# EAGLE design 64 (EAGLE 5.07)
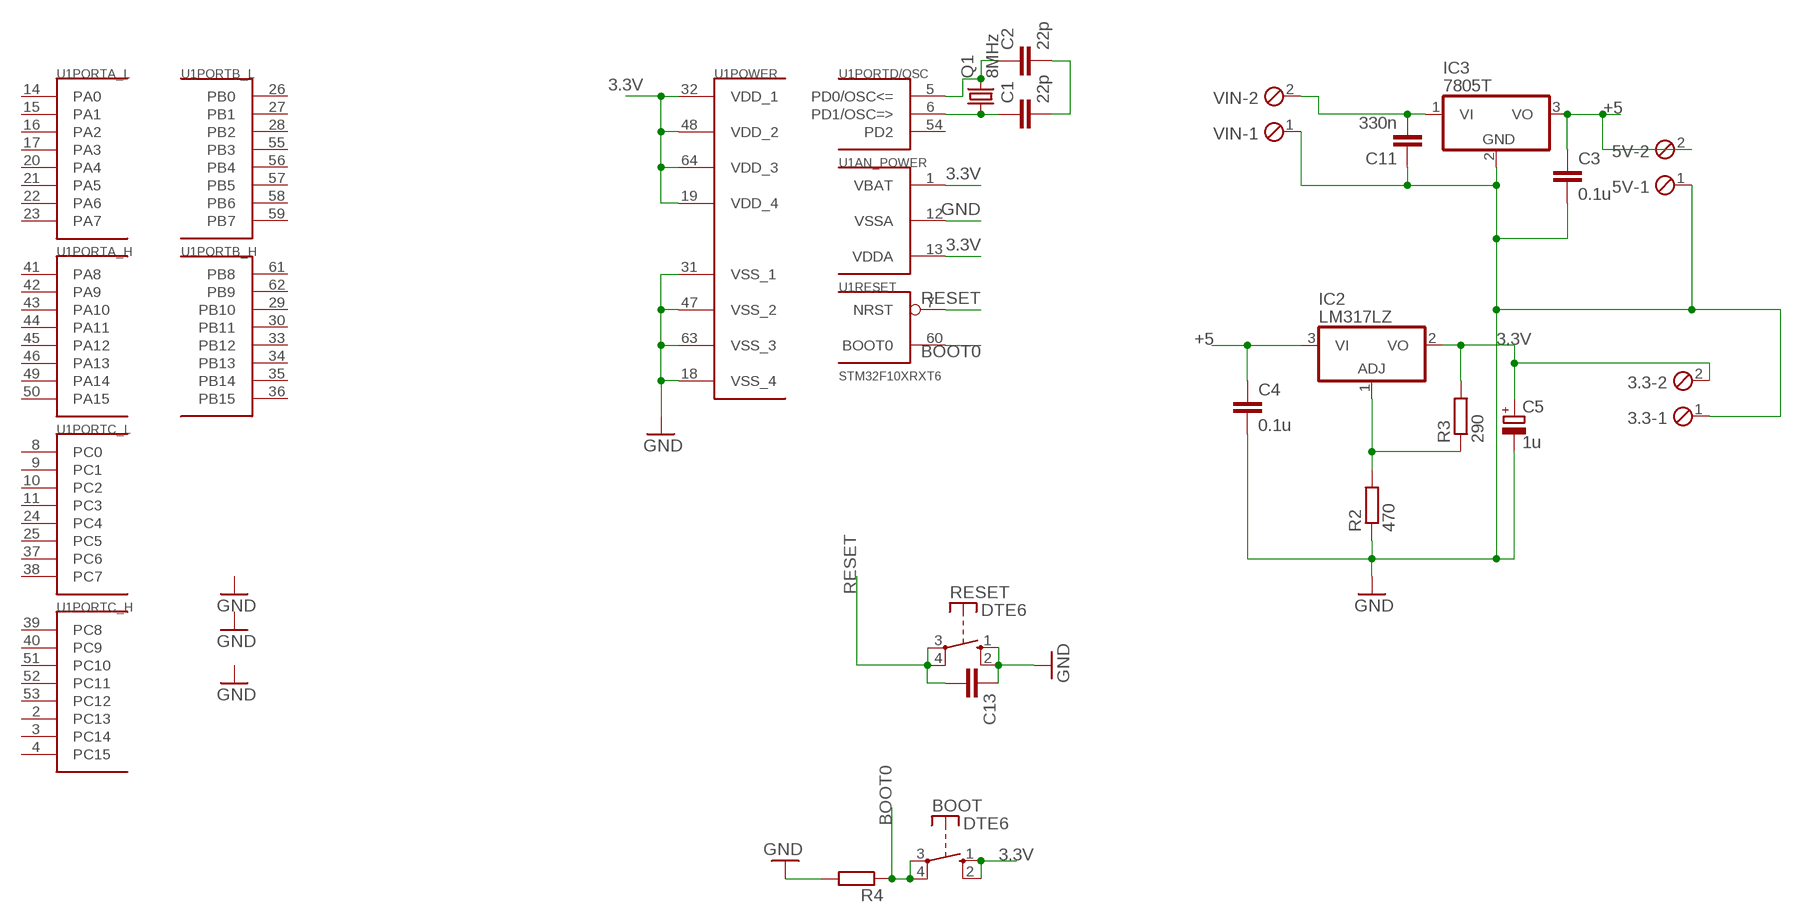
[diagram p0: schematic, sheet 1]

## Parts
3.3  MPT2  [2POL254]
5V  MPT2  [2POL254]
BOOT  DTE6  [DTE6]
C1  22p  C-EUC0805  [C0805]
C2  22p  C-EUC0805  [C0805]
C3  0.1u  C-EUC0805  [C0805]
C4  0.1u  C-EUC0805  [C0805]
C5  1u  CPOL-EUE2.5-6  [E2,5-6]
C11  330n  C-EUC0805  [C0805]
C13  C-EUC0805K  [C0805K]
IC2  LM317LZ  [TO92]
IC3  7805T  [TO220H]
Q1  8MHz  CRYSTALHC49S  [HC49/S]
R2  470  R-EU_R0805  [R0805]
R3  290  R-EU_R0805  [R0805]
R4  R-EU_R0805  [R0805]
RESET  DTE6  [DTE6]
U1  STM32F10XRXT6  [TQFP64]
VIN  MPT2  [2POL254]

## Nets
3.3V: 3.3.2 BOOT.1(S) BOOT.2(S) C5.+ IC2.2(VO) R3.2 U1.1(AN_POWER:VBAT) U1.13(AN_POWER:VDDA) U1.19(POWER:VDD_4) U1.32(POWER:VDD_1) U1.48(POWER:VDD_2) U1.64(POWER:VDD_3)
+5: 5V.2 C3.1 C4.1 IC2.3(VI) IC3.3(VO)
BOOT0: BOOT.3(P) BOOT.4(P) R4.1 U1.60(RESET:BOOT0)
GND: 3.3.1 5V.1 C3.2 C4.2 C5.- C11.1 C13.1 IC3.2(GND) R2.1 R4.2 RESET.1(S) RESET.2(S) U1.12(AN_POWER:VSSA) U1.18(POWER:VSS_4) U1.31(POWER:VSS_1) U1.47(POWER:VSS_2) U1.63(POWER:VSS_3) VIN.1
N$1: C1.2 C2.2
N$5: IC2.1(ADJ) R2.2 R3.1
N$8: C1.1 Q1.1 U1.6(PORTD/OSC:PD1/OSC=>)
N$9: C2.1 Q1.2 U1.5(PORTD/OSC:PD0/OSC<=)
N$36: C11.2 IC3.1(VI) VIN.2
RESET: C13.2 RESET.3(P) RESET.4(P) U1.7(RESET:NRST)
Unconnected: U1.2(PORTC_H:PC13) U1.3(PORTC_H:PC14) U1.4(PORTC_H:PC15) U1.8(PORTC_L:PC0) U1.9(PORTC_L:PC1) U1.10(PORTC_L:PC2) U1.11(PORTC_L:PC3) U1.14(PORTA_L:PA0) U1.15(PORTA_L:PA1) U1.16(PORTA_L:PA2) U1.17(PORTA_L:PA3) U1.20(PORTA_L:PA4) U1.21(PORTA_L:PA5) U1.22(PORTA_L:PA6) U1.23(PORTA_L:PA7) U1.24(PORTC_L:PC4) U1.25(PORTC_L:PC5) U1.26(PORTB_L:PB0) U1.27(PORTB_L:PB1) U1.28(PORTB_L:PB2) U1.29(PORTB_H:PB10) U1.30(PORTB_H:PB11) U1.33(PORTB_H:PB12) U1.34(PORTB_H:PB13) U1.35(PORTB_H:PB14) U1.36(PORTB_H:PB15) U1.37(PORTC_L:PC6) U1.38(PORTC_L:PC7) U1.39(PORTC_H:PC8) U1.40(PORTC_H:PC9) U1.41(PORTA_H:PA8) U1.42(PORTA_H:PA9) U1.43(PORTA_H:PA10) U1.44(PORTA_H:PA11) U1.45(PORTA_H:PA12) U1.46(PORTA_H:PA13) U1.49(PORTA_H:PA14) U1.50(PORTA_H:PA15) U1.51(PORTC_H:PC10) U1.52(PORTC_H:PC11) U1.53(PORTC_H:PC12) U1.54(PORTD/OSC:PD2) U1.55(PORTB_L:PB3) U1.56(PORTB_L:PB4) U1.57(PORTB_L:PB5) U1.58(PORTB_L:PB6) U1.59(PORTB_L:PB7) U1.61(PORTB_H:PB8) U1.62(PORTB_H:PB9)

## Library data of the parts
3.3 5V VIN = con-phoenix-254:MPT2: PHOENIX CONNECTOR
BOOT RESET = switch-misc:DT: ITT SWITCH
C1-C4 C11 C13 = resistor:C-EU: CAPACITOR, European symbol
C5 = resistor:CPOL-EU: POLARIZED CAPACITOR, European symbol
IC2 = linear:*317: Positive VOLTAGE REGULATOR
IC3 = linear:78*: Positive VOLTAGE REGULATOR Source: http://cache.national.com/ds/LM/LM78L05.pdf http://www.fairchildsemi.com/ds/LM/LM7805.pdf
Q1 = crystal:CRYSTAL: CRYSTAL
R2-R4 = resistor:R-EU_: RESISTOR, European symbol
U1 = stm32:STM32F10XRXT6: STM32F101/103 64pin LQFP

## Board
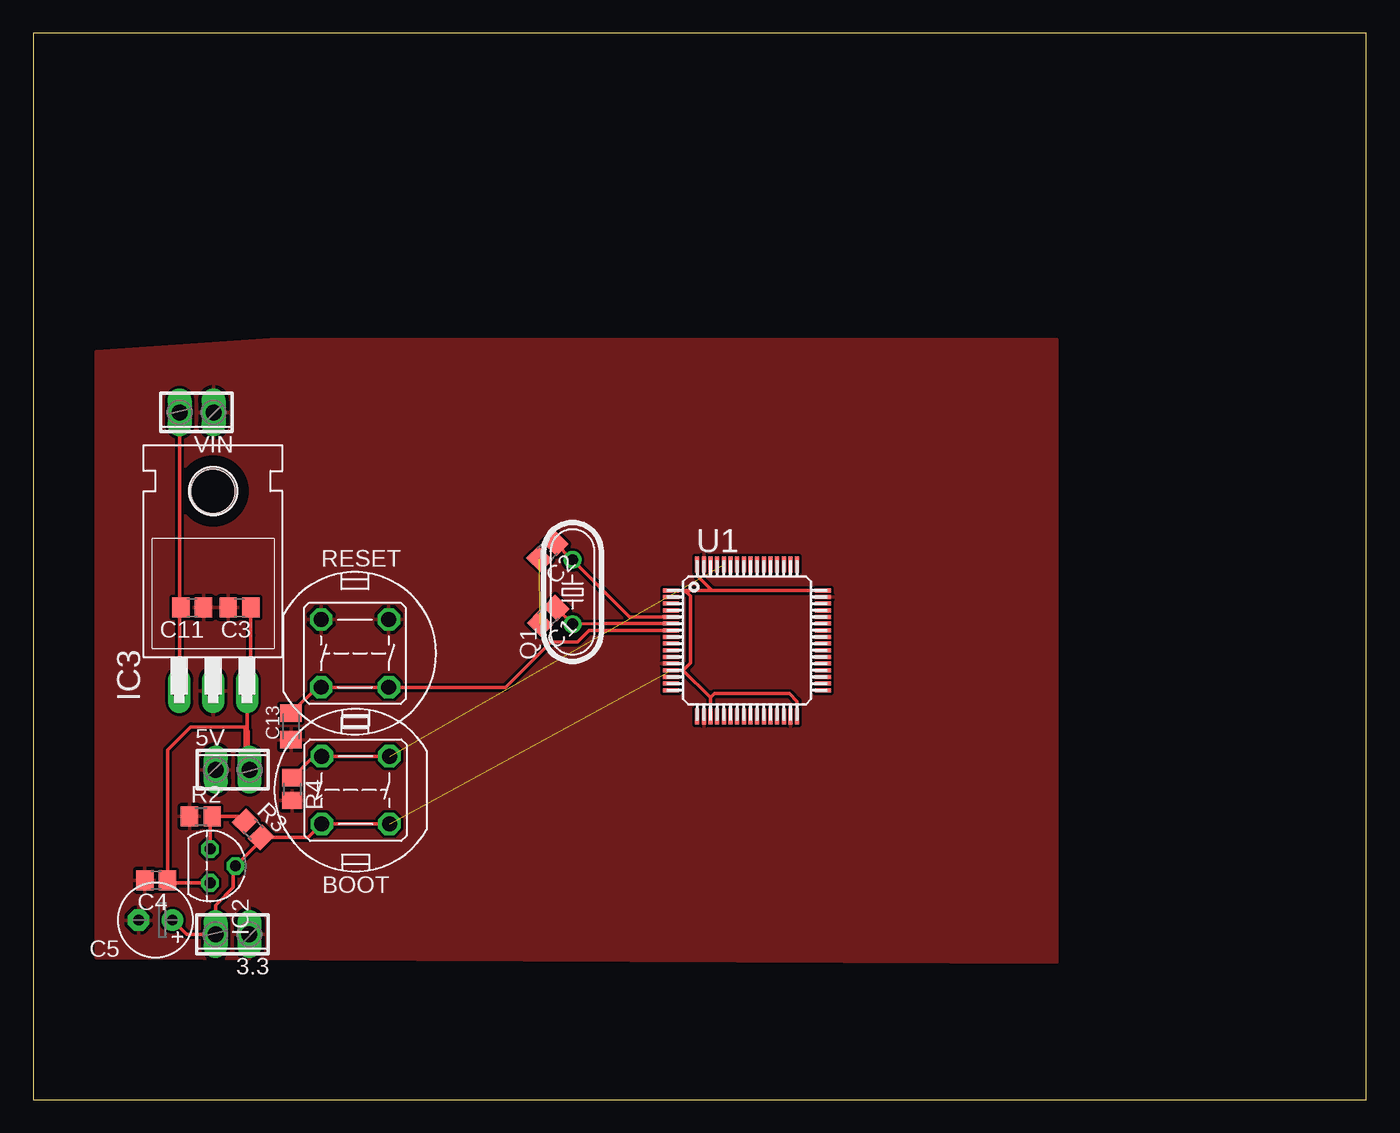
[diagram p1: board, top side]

Size 100 x 80 mm. Coordinates in mm from the lower left corner, seen from the top.
Outline: 0,0 100,0 100,80 0,80 0,0
Copper layers (1*16): Top 0.035mm / dielectric 1.5mm / Bottom 0.035mm
Design rules "default": minimum track width 10mil, minimum drill 24mil, track to track 8mil, track to pad 8mil, pad to pad 8mil, via to via 8mil, smd to smd 8mil, copper to edge 40mil, drill to drill 8mil, minimum pad ring 10mil, minimum via ring 8mil, stop-mask expansion 4mil, vias tented up to drill 0mil, thermal gap 10mil

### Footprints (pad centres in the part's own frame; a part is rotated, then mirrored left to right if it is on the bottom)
2POL254 = drill 1.2 long: 1 -1.27,0; 2 1.27,0
DTE6 = drill 1.118 octagon: 1 -2.54,2.54; 2 2.54,2.54; 3 2.54,-2.54; 4 -2.54,-2.54
C0805 = smd 1.3 x 1.5: 1 -0.85,0; 2 0.85,0
E2,5-6 = drill 0.813 pad 1.6 round: + -1.27,0 | drill 0.813 pad 1.6 octagon: - 1.27,0
C0805K = smd 1.3 x 1.6: 1 -1,0; 2 1,0
TO92 = drill 0.813 octagon: 1 -1.27,0; 2 0,1.905; 3 1.27,0
TO220H = drill 1.118 long: 1 -2.54,-10.16; 2 0,-10.16; 3 2.54,-10.16 | hole 3.302: 0,4.826
HC49/S = drill 0.813 round: 1 -2.413,0; 2 2.413,0
R0805 = smd 1.3 x 1.5: 1 -0.85,0; 2 0.85,0
TQFP64 = smd 1.2 x 0.3: 1 -5.7,3.75; 2 -5.7,3.25; 3 -5.7,2.75; 4 -5.7,2.25; 5 -5.7,1.75; 6 -5.7,1.25; 7 -5.7,0.75; 8 -5.7,0.25; 9 -5.7,-0.25; 10 -5.7,-0.75; 11 -5.7,-1.25; 12 -5.7,-1.75; 13 -5.7,-2.25; 14 -5.7,-2.75; 15 -5.7,-3.25; 16 -5.7,-3.75; 33 5.7,-3.75; 34 5.7,-3.25; 35 5.7,-2.75; 36 5.7,-2.25; 37 5.7,-1.75; 38 5.7,-1.25; 39 5.7,-0.75; 40 5.7,-0.25; 41 5.7,0.25; 42 5.7,0.75; 43 5.7,1.25; 44 5.7,1.75; 45 5.7,2.25; 46 5.7,2.75; 47 5.7,3.25; 48 5.7,3.75 | smd 0.3 x 1.2: 17 -3.75,-5.7; 18 -3.25,-5.7; 19 -2.75,-5.7; 20 -2.25,-5.7; 21 -1.75,-5.7; 22 -1.25,-5.7; 23 -0.75,-5.7; 24 -0.25,-5.7; 25 0.25,-5.7; 26 0.75,-5.7; 27 1.25,-5.7; 28 1.75,-5.7; 29 2.25,-5.7; 30 2.75,-5.7; 31 3.25,-5.7; 32 3.75,-5.7; 49 3.75,5.7; 50 3.25,5.7; 51 2.75,5.7; 52 2.25,5.7; 53 1.75,5.7; 54 1.25,5.7; 55 0.75,5.7; 56 0.25,5.7; 57 -0.25,5.7; 58 -0.75,5.7; 59 -1.25,5.7; 60 -1.75,5.7; 61 -2.25,5.7; 62 -2.75,5.7; 63 -3.25,5.7; 64 -3.75,5.7

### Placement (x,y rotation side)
3.3  14.94,12.4 180 top
5V  14.96,24.74 0 top
BOOT  24.18,23.22 180 top
C1  [C0805]  38.62,36.29 225 top
C2  [C0805]  38.57,41.16 225 top
C3  15.47,36.91 180 top
C4  9.22,16.46 180 top
C5  9.17,13.46 180 top
C11  [C0805]  11.91,36.91 180 top
C13  19.33,27.99 90 top
IC2  13.26,17.53 270 top
IC3  13.49,40.82 0 top
Q1  [HC49/S]  40.45,38.08 90 top
R2  12.57,21.23 0 top
R3  16.48,20.27 315 top
R4  19.43,23.29 270 top
RESET  24.13,33.48 0 top
U1  53.55,34.45 0 top
VIN  12.24,51.56 180 top

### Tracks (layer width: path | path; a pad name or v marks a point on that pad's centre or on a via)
3.3V  (1 unrouted)
  Top 0.254: 50.8,30.16 U1.19 | 48.76,32.21 50.8,30.16 | 48.76,32.21 U1.13 | 48.87,38.2 U1.1 | 48.87,38.2 49.3,37.77 49.3,32.74 48.76,32.21 | 50.92,38.2 50.98,38.2 U1.48 | 50.92,38.2 49.84,39.28 49.84,40.12 U1.64 | U1.32 57.3,29.88 56.71,30.46 51.11,30.46 50.8,30.16 | C5.+ 11.51,12.39 3.3.2 13.66,14.55 15.01,15.9 15.01,17.37 IC2.2 17.09,19.45 R3.2 20.63,19.67 BOOT.2 BOOT.1 | 48.87,38.2 50.92,38.2
+5
  Top 0.254: 5V.2 16.03,24.94 IC3.3 16.32,30.95 16.32,34.85 C3.1 | IC2.3 9.74,16.26 C4.1 10.07,26.23 11.81,27.96 15.9,27.96 15.9,25.07 5V.2 | 5V.2 16.1,24.87 16.1,27.66
BOOT0  (1 unrouted)
  Top 0.254: BOOT.4 BOOT.3 21.05,25.76 R4.1
GND
  pour Top: 17.81,57.02 76.78,57.02 76.78,10.31 4.72,10.62 4.72,56.11
N$1  (1 unrouted)
N$5
  Top 0.254: R3.1 15.52,21.23 R2.2 13.26,21.07 IC2.1
N$8
  Top 0.254: U1.6 42.85,35.7 Q1.1 39.24,36.89 C1.1
N$9
  Top 0.254: C2.1 40.43,40.5 Q1.2 44.75,36.2 U1.5
N$36
  Top 0.254: VIN.2 10.97,36.52 10.97,30.68 IC3.1 10.9,30.61
  Top 0.406: C11.2 10.97,36.91 10.97,36.52
RESET
  Top 0.254: U1.7 41.68,35.2 40.82,34.34 38.84,34.34 35.43,30.94 RESET.3 RESET.4 21.28,30.94 C13.2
